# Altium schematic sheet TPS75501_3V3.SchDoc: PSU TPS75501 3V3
size A4; Organization: Altium Limited.; Address1: Level 3, 12a Rodborough Rd; Address2: Frenchs Forest 2086; Address3: NSW; Address4: AUSTRALIA; DocumentNumber: 3; Revision: 6; SheetNumber: 3; SheetTotal: 3
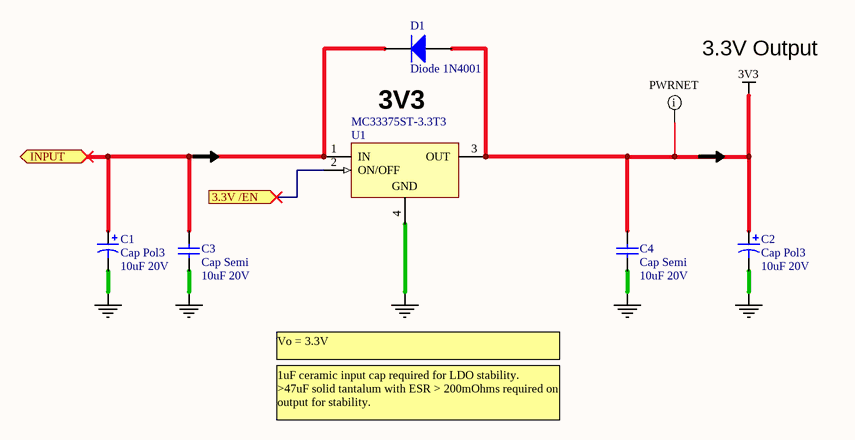
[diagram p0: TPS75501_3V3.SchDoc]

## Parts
C1  Cap Pol3  value 10uF 20V  [2220]
C2  Cap Pol3  value 10uF 20V  [2220]
C3  Cap Semi  value 10uF 20V  [C1206]
C4  Cap Semi  value 10uF 20V  [C1206]
D1  Diode 1N4001  [DO-41]
U1  MC33375ST-3.3T3  [318E-04]

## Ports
3.3V /EN (in), INPUT (bidir)

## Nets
3V3: C2.1 C4.1 D1.1(A) U1.3(OUT)
GND: C1.2 C2.2 C3.2 C4.2 U1.4(GND)
3.3V /EN: U1.2(ON/OFF) ; port 3.3V /EN
INPUT: C1.1 C3.1 D1.2(K) U1.1(IN) ; port INPUT

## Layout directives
net class PWRNET: 3V3

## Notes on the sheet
- 3.3V Output
- 3V3
- Vo = 3.3V
- 1uF ceramic input cap required for LDO stability.
  >47uF solid tantalum with ESR > 200mOhms required on output for stability.

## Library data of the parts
C1 C2 = Cap Pol3: Polarized Capacitor (Surface Mount)
C3 C4 = Cap Semi: Capacitor (Semiconductor SIM Model)
D1 = Diode 1N4001: 1 Amp General Purpose Rectifier
U1 = MC33375ST-3.3T3: Low Dropout 300mA Voltage Regulator with ON/OFF Control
